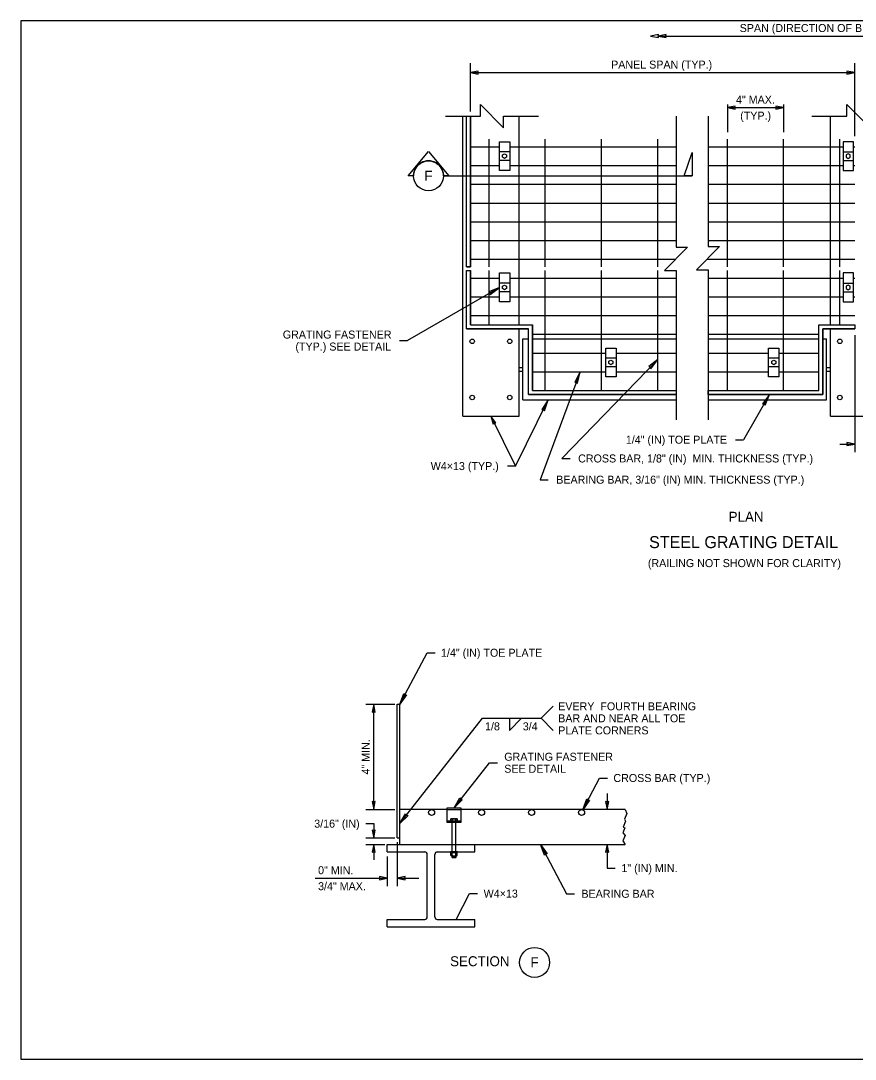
# Model space of a CAD drawing. Extents: x 99862 to 103151, y 100000 to 108076.
# Drawn here: x 99862 to 101531, y 106000 to 108076 of the extents above; entities that cross this region are included whole.
import ezdxf

# ---------------------------------------------------------------- set-up
doc = ezdxf.new("R2010")
doc.units = 0
for name, color, linetype in [('Level 1', 7, 'Continuous'), ('Level 15', 7, 'Continuous'), ('Level 17', 7, 'Continuous'), ('Level 20', 7, 'Continuous'), ('Level 25', 7, 'Continuous'), ('Level 30', 7, 'Continuous'), ('Level 36', 7, 'Continuous'), ('Level 4', 7, 'Continuous'), ('Level 60', 7, 'Continuous'), ('Level 9', 7, 'Continuous')]:
    doc.layers.add(name, color=color, linetype=linetype)

msp = doc.modelspace()

# ---------------------------------------------------------------- linework, layer by layer
at = {"layer": 'Level 1'}
msp.add_lwpolyline([(99862, 105999.5), (103151, 105999.5), (103151, 108075.5), (99862, 108075.5)], close=True, dxfattribs=at)
at = {"layer": 'Level 15'}
for p, q in [((100761.4, 107894.2), (100761.4, 107990.8)), ((101530.5, 107845.1), (101530.5, 107990.8)), ((101275.5, 107908.3), (101275.5, 107853)), ((101275.5, 107901.8), (101388, 107901.8)), ((101388, 107908.3), (101388, 107853)), ((100761.4, 107852), (100761.4, 107875.6)), ((100819.5, 107542.4), (100635.7, 107436.2)), ((100619.7, 107436.2), (100635.7, 107436.2)), ((101530.5, 107447.2), (101530.5, 107213.2)), ((101136.4, 107398.5), (100944.1, 107200.5)), ((100980.9, 107373.7), (100901.2, 107158.1)), ((101360.1, 107328.2), (101308, 107238)), ((101292, 107238), (101308, 107238)), ((101500.5, 107229.2), (101530.5, 107229.2)), ((100851.8, 107185.3), (100835.8, 107185.3)), ((100944.1, 107200.5), (100961, 107200.5)), ((100901.2, 107158.1), (100917.2, 107158.1)), ((100620.3, 106709), (100674.7, 106812.1)), ((100674.7, 106812.1), (100690.7, 106812.1)), ((100552.2, 106709), (100610.3, 106709)), ((100568.2, 106499), (100568.2, 106709)), ((100620.3, 106470.5), (100785.9, 106681)), ((100728.7, 106502), (100799.7, 106592.2)), ((100799.7, 106592.2), (100815.7, 106592.2)), ((100986.2, 106498.4), (101019.6, 106561.7)), ((101019.6, 106561.7), (101035.6, 106561.7)), ((101035.1, 106530.8), (101035.1, 106499)), ((100552.2, 106499), (100610.3, 106499)), ((100552.2, 106470.5), (100568.2, 106470.5)), ((100568.2, 106470.5), (100568.2, 106442)), ((100552.2, 106442), (100610.3, 106442)), ((100552.2, 106429), (100590.3, 106429)), ((100568.2, 106429), (100568.2, 106398)), ((100615.3, 106433.7), (100615.3, 106345.4)), ((100901.5, 106429), (100953.6, 106330.3)), ((101035.1, 106429), (101035.1, 106381.5)), ((100595.3, 106404.5), (100595.3, 106345.4)), ((101035.1, 106381.5), (101051.3, 106381.5)), ((100450.9, 106361.4), (100595.3, 106361.4)), ((100615.3, 106361.4), (100658.3, 106361.4)), ((100732.8, 106279), (100760, 106330.6)), ((100760, 106330.6), (100776, 106330.6)), ((100953.6, 106330.3), (100969.6, 106330.3))]:
    msp.add_line(p, q, dxfattribs=at)
for points in [[(101122.1, 108045), (101137.8, 108042), (101137.1, 108045), (101137.8, 108048.1)], [(101137.1, 108045), (101152.8, 108042), (101152.1, 108045), (101152.8, 108048.1)], [(100761.4, 107971.9), (100777.1, 107968.8), (100776.4, 107971.9), (100777.1, 107975)], [(101530.5, 107971.9), (101514.7, 107975), (101515.5, 107971.9), (101514.7, 107968.8)], [(101275.5, 107901.8), (101291.2, 107898.8), (101290.5, 107901.8), (101291.2, 107904.9)], [(101388, 107901.8), (101372.2, 107904.9), (101373, 107901.8), (101372.2, 107898.8)], [(100819.5, 107542.4), (100798.3, 107533.6), (100800.7, 107531.5), (100801.3, 107528.4)], [(101136.4, 107398.5), (101118.4, 107384.2), (101121.2, 107382.8), (101122.6, 107380)], [(100980.9, 107373.7), (100970.2, 107353.3), (100973.3, 107353.2), (100975.8, 107351.2)], [(100917.3, 107317.4), (100904.5, 107298.3), (100907.6, 107297.9), (100909.9, 107295.6)], [(101360.1, 107328.2), (101346.1, 107309.9), (101349.2, 107309.3), (101351.3, 107306.9)], [(100802.7, 107284.8), (100806.9, 107269.3), (100809.3, 107271.3), (100812.4, 107272)], [(101530.5, 107229.2), (101514.7, 107232.3), (101515.5, 107229.2), (101514.7, 107226.2)], [(100620.3, 106709), (100628.3, 106730.5), (100630.4, 106728.2), (100633.6, 106727.8)], [(100568.2, 106709), (100565.1, 106693.2), (100568.2, 106694), (100571.2, 106693.2)], [(100728.7, 106502), (100740.4, 106521.8), (100742.1, 106519.1), (100745.1, 106518.1)], [(100986.2, 106498.4), (100994.2, 106520), (100996.4, 106517.7), (100999.5, 106517.2)], [(100568.2, 106499), (100571.2, 106514.7), (100568.2, 106514), (100565.1, 106514.7)], [(101035.1, 106499), (101038.1, 106514.7), (101035.1, 106514), (101032, 106514.7)], [(100620.3, 106470.5), (100632, 106490.3), (100633.7, 106487.6), (100636.7, 106486.6)], [(100568.2, 106442), (100571.2, 106457.7), (100568.2, 106457), (100565.1, 106457.7)], [(100568.2, 106429), (100565.1, 106413.2), (100568.2, 106414), (100571.2, 106413.2)], [(100901.5, 106429), (100914.8, 106410.2), (100911.7, 106409.7), (100909.6, 106407.4)], [(101035.1, 106429), (101032, 106413.2), (101035.1, 106414), (101038.1, 106413.2)], [(100595.3, 106361.4), (100579.5, 106364.5), (100580.3, 106361.4), (100579.5, 106358.3)], [(100615.3, 106361.4), (100631, 106358.3), (100630.3, 106361.4), (100631, 106364.5)]]:
    msp.add_lwpolyline(points, close=True, dxfattribs=at)
for points in [[(101137.1, 108045), (101870.8, 108045)], [(100761.4, 107971.9), (101530.5, 107971.9)], [(100711.5, 107884.9), (100781.5, 107884.9), (100781.5, 107908.1), (100827.9, 107861.7), (100827.9, 107884.9), (100897.9, 107884.9)], [(101444.6, 107884.8), (101514.6, 107884.8), (101514.6, 107908), (101561, 107861.5), (101561, 107884.8), (101631, 107884.8)], [(101172.8, 107884.9), (101172.8, 107622.9), (101196.1, 107622.9), (101149.6, 107576.5), (101172.8, 107576.5), (101172.8, 107277.9)], [(101236.9, 107884.9), (101236.9, 107624.4), (101260.1, 107624.4), (101213.7, 107577.9), (101236.9, 107577.9), (101236.9, 107277.9)], [(100802.7, 107284.8), (100851.8, 107185.3), (100917.3, 107317.4)]]:
    msp.add_lwpolyline(points, dxfattribs=at)
at = {"layer": 'Level 17'}
for p, q in [((100753.4, 107583.7), (100753.4, 107884.9)), ((100761.4, 107583.7), (100761.4, 107884.9)), ((100753.4, 107583.7), (100761.4, 107583.7)), ((100753.4, 107459.4), (100753.4, 107576.2)), ((100753.4, 107576.2), (100761.4, 107576.2)), ((100761.4, 107467.4), (100761.4, 107576.2)), ((100753.4, 107459.4), (100877.7, 107459.4)), ((100761.4, 107467.4), (100885.7, 107467.4)), ((100877.7, 107328.2), (100877.7, 107459.4)), ((100885.7, 107336.2), (100885.7, 107467.4)), ((101458.7, 107336.2), (101458.7, 107467.4)), ((101458.7, 107467.4), (101530.5, 107467.4)), ((101466.7, 107328.2), (101466.7, 107459.4)), ((101466.7, 107459.4), (101530.5, 107459.4)), ((101530.5, 107467.4), (101530.5, 107459.4)), ((100885.7, 107336.2), (101172.8, 107336.2)), ((101236.9, 107336.2), (101458.7, 107336.2)), ((100877.7, 107328.2), (101172.8, 107328.2)), ((101236.9, 107328.2), (101466.7, 107328.2))]:
    msp.add_line(p, q, dxfattribs=at)
at = {"layer": 'Level 20'}
for p, q in [((100707.7, 107765.5), (101204.9, 107765.5)), ((100902.9, 106681), (100926.9, 106705)), ((100785.9, 106681), (100902.9, 106681)), ((100839.7, 106681), (100839.7, 106657)), ((100839.7, 106657), (100863.7, 106681)), ((100902.9, 106681), (100926.9, 106657))]:
    msp.add_line(p, q, dxfattribs=at)
at = {"layer": 'Level 25'}
for points in [[(100753.4, 107884.9), (100761.4, 107884.9), (100761.4, 107583.7), (100753.4, 107583.7)], [(100753.4, 107576.2), (100761.4, 107576.2), (100761.4, 107467.4), (100885.7, 107467.4), (100885.7, 107336.2), (101172.8, 107336.2), (101172.8, 107328.2), (100877.7, 107328.2), (100877.7, 107459.4), (100753.4, 107459.4)], [(101236.9, 107336.2), (101458.7, 107336.2), (101458.7, 107467.4), (101530.5, 107467.4), (101530.5, 107459.4), (101466.7, 107459.4), (101466.7, 107328.2), (101236.9, 107328.2)]]:
    msp.add_lwpolyline(points, close=True, dxfattribs=at)
at = {"layer": 'Level 30'}
for p, q in [((100722.5, 106479.8), (100723.4, 106480.3)), ((100722.5, 106475.6), (100722.5, 106479.8)), ((100723.4, 106480.3), (100734, 106480.3)), ((100725.6, 106475.6), (100725.6, 106479.7)), ((100731.7, 106479.7), (100731.7, 106475.6)), ((100734, 106480.3), (100734.8, 106479.8)), ((100734.8, 106479.8), (100734.8, 106475.6)), ((100742.5, 106475.6), (100714.9, 106475.6)), ((100725.1, 106429), (100725.1, 106472.6)), ((100732.2, 106429), (100732.2, 106472.6)), ((100723.7, 106406.1), (100733.6, 106406.1)), ((100725.1, 106405.4), (100732.2, 106405.4)), ((100725.1, 106404.1), (100732.2, 106404.1)), ((100732.2, 106402.7), (100725.1, 106402.7)), ((100725.3, 106406.6), (100725.3, 106413)), ((100725.8, 106404.7), (100731.5, 106404.7)), ((100725.8, 106403.4), (100731.5, 106403.4)), ((100732, 106413), (100732, 106406.6))]:
    msp.add_line(p, q, dxfattribs=at)
for points in [[(100829.9, 107800.3), (100825.9, 107802.6), (100825.9, 107807.2), (100829.9, 107809.5), (100833.9, 107807.2), (100833.9, 107802.6)], [(101517.4, 107800.3), (101521.4, 107802.6), (101521.4, 107807.2), (101517.4, 107809.5), (101513.5, 107807.2), (101513.5, 107802.6)], [(100829.9, 107537.8), (100825.9, 107540.1), (100825.9, 107544.7), (100829.9, 107547), (100833.9, 107544.7), (100833.9, 107540.1)], [(101517.4, 107537.8), (101521.4, 107540.1), (101521.4, 107544.7), (101517.4, 107547), (101513.5, 107544.7), (101513.5, 107540.1)], [(101042.6, 107387.8), (101038.6, 107390.1), (101038.6, 107394.7), (101042.6, 107397), (101046.6, 107394.7), (101046.6, 107390.1)], [(101368.3, 107387.8), (101364.3, 107390.1), (101364.3, 107394.7), (101368.3, 107397), (101372.2, 107394.7), (101372.2, 107390.1)]]:
    msp.add_lwpolyline(points, close=True, dxfattribs=at)
for points in [[(100721.6, 106414), (100721.6, 106413), (100735.7, 106413), (100735.7, 106414), (100721.6, 106414)], [(100735.3, 106406.6), (100735.3, 106413), (100722, 106413), (100722, 106406.6)], [(100732.2, 106406.1), (100732.2, 106402.7), (100731.5, 106402.1), (100725.8, 106402.1), (100725.1, 106402.7), (100725.1, 106406.1)]]:
    msp.add_lwpolyline(points, dxfattribs=at)
for centre, radius, start, end in [((100724, 106477.7), 2.59, 52.8251, 125.1741), ((100728.7, 106471.1), 9.14, 70.4632, 109.5368), ((100733.3, 106477.7), 2.59, 54.8259, 127.1749), ((100723.7, 106408.9), 2.87, 234.7356, 305.2644), ((100728.7, 106417.5), 11.5, 253.2213, 286.7787), ((100733.6, 106408.9), 2.87, 234.7356, 305.2644)]:
    msp.add_arc(centre, radius, start, end, dxfattribs=at)
at = {"layer": 'Level 36'}
for p, q in [((100714.9, 106499), (100742.5, 106499)), ((100725.1, 106414), (100725.1, 106429)), ((100732.2, 106414), (100732.2, 106429))]:
    msp.add_line(p, q, dxfattribs=at)
at = {"layer": 'Level 4'}
for p, q in [((100746.4, 107284.8), (100746.4, 107884.9)), ((100858.9, 107467.4), (100858.9, 107884.9)), ((101481.7, 107467.4), (101481.7, 107884.8)), ((100798.9, 107583.7), (100798.9, 107838.7)), ((100911.4, 107583.7), (100911.4, 107838.7)), ((101023.9, 107583.7), (101023.9, 107838.7)), ((101136.4, 107583.7), (101136.4, 107838.7)), ((101275.5, 107583.7), (101275.5, 107838.7)), ((101388, 107583.7), (101388, 107838.7)), ((101500.5, 107583.7), (101500.5, 107838.7)), ((100761.4, 107823.7), (100819.5, 107823.7)), ((100840.2, 107813.5), (100819.5, 107813.5)), ((100840.2, 107823.7), (101172.8, 107823.7)), ((101236.9, 107823.7), (101507.1, 107823.7)), ((101507.1, 107813.5), (101527.8, 107813.5)), ((101527.8, 107823.7), (101530.5, 107823.7)), ((100761.4, 107786.2), (100819.5, 107786.2)), ((100840.2, 107796.3), (100819.5, 107796.3)), ((100840.2, 107786.2), (101172.8, 107786.2)), ((101236.9, 107786.2), (101507.1, 107786.2)), ((101507.1, 107796.3), (101527.8, 107796.3)), ((101527.8, 107786.2), (101530.5, 107786.2)), ((100761.4, 107748.7), (101172.8, 107748.7)), ((101236.9, 107748.7), (101530.5, 107748.7)), ((100761.4, 107711.2), (101172.8, 107711.2)), ((101236.9, 107711.2), (101530.5, 107711.2)), ((100761.4, 107673.7), (101172.8, 107673.7)), ((101236.9, 107673.7), (101530.5, 107673.7)), ((100761.4, 107636.2), (101172.8, 107636.2)), ((101236.9, 107636.2), (101530.5, 107636.2)), ((100761.4, 107598.7), (101171.8, 107598.7)), ((101234.4, 107598.7), (101530.5, 107598.7)), ((100761.4, 107561.2), (100819.5, 107561.2)), ((100798.9, 107467.4), (100798.9, 107576.2)), ((100840.2, 107561.2), (101172.8, 107561.2)), ((100911.4, 107336.2), (100911.4, 107576.2)), ((101023.9, 107336.2), (101023.9, 107576.2)), ((101136.4, 107336.2), (101136.4, 107576.2)), ((101236.9, 107561.2), (101507.1, 107561.2)), ((101275.5, 107336.2), (101275.5, 107576.2)), ((101388, 107336.2), (101388, 107576.2)), ((101500.5, 107467.4), (101500.5, 107576.2)), ((101527.8, 107561.2), (101530.5, 107561.2)), ((100840.2, 107551), (100819.5, 107551)), ((101507.1, 107551), (101527.8, 107551)), ((100761.4, 107523.7), (100819.5, 107523.7)), ((100840.2, 107533.8), (100819.5, 107533.8)), ((100840.2, 107523.7), (101172.8, 107523.7)), ((101236.9, 107523.7), (101507.1, 107523.7)), ((101507.1, 107533.8), (101527.8, 107533.8)), ((101527.8, 107523.7), (101530.5, 107523.7)), ((100761.4, 107486.2), (101172.8, 107486.2)), ((101236.9, 107486.2), (101530.5, 107486.2)), ((100858.9, 107284.8), (100858.9, 107459.4)), ((101481.7, 107284.8), (101481.7, 107459.4)), ((100866.4, 107317.4), (100866.4, 107439.5)), ((100866.4, 107439.5), (100877.7, 107439.5)), ((100885.7, 107448.7), (101172.8, 107448.7)), ((100885.7, 107439.5), (101172.8, 107439.5)), ((101236.9, 107448.7), (101458.7, 107448.7)), ((101236.9, 107439.5), (101458.7, 107439.5)), ((101466.7, 107439.5), (101474.2, 107439.5)), ((101474.2, 107317.4), (101474.2, 107439.5)), ((100885.7, 107411.2), (101032.2, 107411.2)), ((101052.9, 107401), (101032.2, 107401)), ((101052.9, 107411.2), (101172.8, 107411.2)), ((101236.9, 107411.2), (101357.9, 107411.2)), ((101378.6, 107401), (101357.9, 107401)), ((101378.6, 107411.2), (101458.7, 107411.2)), ((100858.9, 107382.2), (100866.4, 107382.2)), ((100858.9, 107374.7), (100866.4, 107374.7)), ((100885.7, 107373.7), (101032.2, 107373.7)), ((101052.9, 107383.8), (101032.2, 107383.8)), ((101052.9, 107373.7), (101172.8, 107373.7)), ((101236.9, 107373.7), (101357.9, 107373.7)), ((101378.6, 107383.8), (101357.9, 107383.8)), ((101378.6, 107373.7), (101458.7, 107373.7)), ((101474.2, 107382.2), (101481.7, 107382.2)), ((101474.2, 107374.7), (101481.7, 107374.7)), ((100885.7, 107336.2), (101172.8, 107336.2)), ((101236.9, 107336.2), (101458.7, 107336.2)), ((100866.4, 107317.4), (101172.8, 107317.4)), ((101236.9, 107317.4), (101474.2, 107317.4)), ((100746.4, 107284.8), (100858.9, 107284.8)), ((101481.7, 107284.8), (101594.2, 107284.8)), ((100615.3, 106442), (100615.3, 106709)), ((100615.3, 106709), (100620.3, 106709)), ((100620.3, 106429), (100620.3, 106709)), ((100620.3, 106429), (100620.3, 106598)), ((100714.9, 106499), (100620.3, 106499)), ((101071.2, 106499), (100742.5, 106499)), ((100615.3, 106442), (100620.3, 106442)), ((100595.3, 106429), (100770.3, 106429)), ((100595.3, 106414), (100595.3, 106429)), ((100770.3, 106414), (100770.3, 106429)), ((100770.3, 106429), (101071.2, 106429)), ((100595.3, 106414), (100670.3, 106414)), ((100675.3, 106284), (100675.3, 106409)), ((100690.3, 106284), (100690.3, 106409)), ((100695.3, 106414), (100770.3, 106414)), ((100595.3, 106264), (100595.3, 106279)), ((100595.3, 106279), (100670.3, 106279)), ((100695.3, 106279), (100770.3, 106279)), ((100770.3, 106264), (100770.3, 106279)), ((100595.3, 106264), (100770.3, 106264))]:
    msp.add_line(p, q, dxfattribs=at)
for points in [[(100819.5, 107833.8), (100840.2, 107833.8), (100840.2, 107776), (100819.5, 107776)], [(101527.8, 107833.8), (101507.1, 107833.8), (101507.1, 107776), (101527.8, 107776)], [(100819.5, 107571.3), (100840.2, 107571.3), (100840.2, 107513.5), (100819.5, 107513.5)], [(101527.8, 107571.3), (101507.1, 107571.3), (101507.1, 107513.5), (101527.8, 107513.5)], [(101032.2, 107421.3), (101052.9, 107421.3), (101052.9, 107363.5), (101032.2, 107363.5)], [(101357.9, 107421.3), (101378.6, 107421.3), (101378.6, 107363.5), (101357.9, 107363.5)], [(100742.5, 106472.6), (100714.9, 106472.6), (100714.9, 106502), (100742.5, 106502)]]:
    msp.add_lwpolyline(points, close=True, dxfattribs=at)
msp.add_lwpolyline([(101071.2, 106499), (101074.2, 106490.5), (101069.5, 106479.5), (101071.7, 106475.1), (101066.8, 106463.7), (101070.5, 106462.1), (101066.3, 106452.1), (101071.4, 106446.7), (101066.5, 106436.3), (101071.2, 106429)], dxfattribs=at)
for centre, radius in [((100765.2, 107434.8), 4.5), ((100840.2, 107434.8), 4.5), ((101500.5, 107434.8), 4.5), ((100765.2, 107322.3), 4.5), ((100840.2, 107322.3), 4.5), ((101500.5, 107322.3), 4.5), ((100683.9, 106492.8), 6.03), ((100783.9, 106492.8), 6.03), ((100883.9, 106492.8), 6.03), ((100983.9, 106492.8), 6.03)]:
    msp.add_circle(centre, radius, dxfattribs=at)
for centre, start, end in [((100670.3, 106409), 0, 90), ((100695.3, 106409), 90, 180), ((100670.3, 106284), 270, 0), ((100695.3, 106284), 180, 270)]:
    msp.add_arc(centre, 5, start, end, dxfattribs=at)
at = {"layer": 'Level 60'}
msp.add_line((99862, 105999.5), (99862, 105999.5), dxfattribs=at)
at = {"layer": 'Level 9'}
for p, q in [((100637.1, 107765.5), (100677.7, 107814)), ((100677.7, 107814), (100718.3, 107765.5)), ((100647.7, 107765.5), (100637.1, 107765.5)), ((100718.3, 107765.5), (100707.7, 107765.5))]:
    msp.add_line(p, q, dxfattribs=at)
msp.add_lwpolyline([(101189.3, 107765.5), (101204.9, 107812.4), (101204.9, 107765.5)], close=True, dxfattribs=at)
for centre in [(100677.7, 107765.5), (100890, 106193)]:
    msp.add_circle(centre, 30, dxfattribs=at)
msp.add_arc((100677.7, 107765.5), 30, 359.9978, 180.0022, dxfattribs=at)

# ---------------------------------------------------------------- texts
at = {"layer": 'Level 20'}
for s, height, p in [('SPAN (DIRECTION OF BEARING BARS)', 16, (101300.2, 108053)), ('PANEL SPAN (TYP.)', 16, (101043, 107979.9)), ('4" MAX.', 16, (101292.8, 107909.8)), ('(TYP.)', 16, (101301.2, 107877.8)), ('F', 20, (100669.4, 107755.7)), ('GRATING FASTENER', 16, (100386.2, 107440.2)), ('(TYP.) SEE DETAIL', 16, (100411.5, 107416.2)), ('1/4" (IN) TOE PLATE', 16, (101072.4, 107230)), ('CROSS BAR, 1/8" (IN)  MIN. THICKNESS (TYP.)', 16, (100977, 107192.5)), ('W4×13 (TYP.)', 16, (100682.1, 107177.3)), ('BEARING BAR, 3/16" (IN) MIN. THICKNESS (TYP.)', 16, (100933.2, 107150.1)), ('PLAN', 20, (101278.1, 107073.9)), ('STEEL GRATING DETAIL', 24, (101119, 107021.3)), ('(RAILING NOT SHOWN FOR CLARITY)', 16, (101116.5, 106983.3)), ('1/4" (IN) TOE PLATE', 16, (100702.7, 106804.1)), ('EVERY  FOURTH BEARING', 16, (100937.1, 106697)), ('BAR AND NEAR ALL TOE', 16, (100937.1, 106673)), ('1/8', 16, (100790.8, 106657)), ('3/4', 16, (100866.3, 106657)), ('PLATE CORNERS', 16, (100937.1, 106648.9)), ('GRATING FASTENER', 16, (100829.2, 106596.2)), ('SEE DETAIL', 16, (100829.2, 106572.2)), ('CROSS BAR (TYP.)', 16, (101047.6, 106553.7)), ('3/16" (IN)', 16, (100449.1, 106462.5)), ('0" MIN.', 16, (100456.8, 106369.4)), ('1" (IN) MIN.', 16, (101063.6, 106373.5)), ('3/4" MAX.', 16, (100456.8, 106337.4)), ('W4×13', 16, (100788, 106322.6)), ('BEARING BAR', 16, (100983.6, 106322.3)), ('SECTION', 20, (100720.9, 106185.4)), ('F', 20, (100881.7, 106183.2))]:
    msp.add_text(s, height=height, dxfattribs=at).set_placement(p)
msp.add_text('4" MIN.', height=16, rotation=90, dxfattribs=at).set_placement((100560.2, 106568.7))

doc.saveas('drawing.dxf')
